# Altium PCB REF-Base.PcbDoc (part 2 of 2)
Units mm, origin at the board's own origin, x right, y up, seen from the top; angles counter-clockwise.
Board outline 48.01 x 58 mm, 4 copper layers (Top1, VCC, GND, Bottom2), stack 1.833 mm thick; 98 components, 129 nets, 444 pads, 192 vias.
Unrouted connection lines stored in the file: 57.
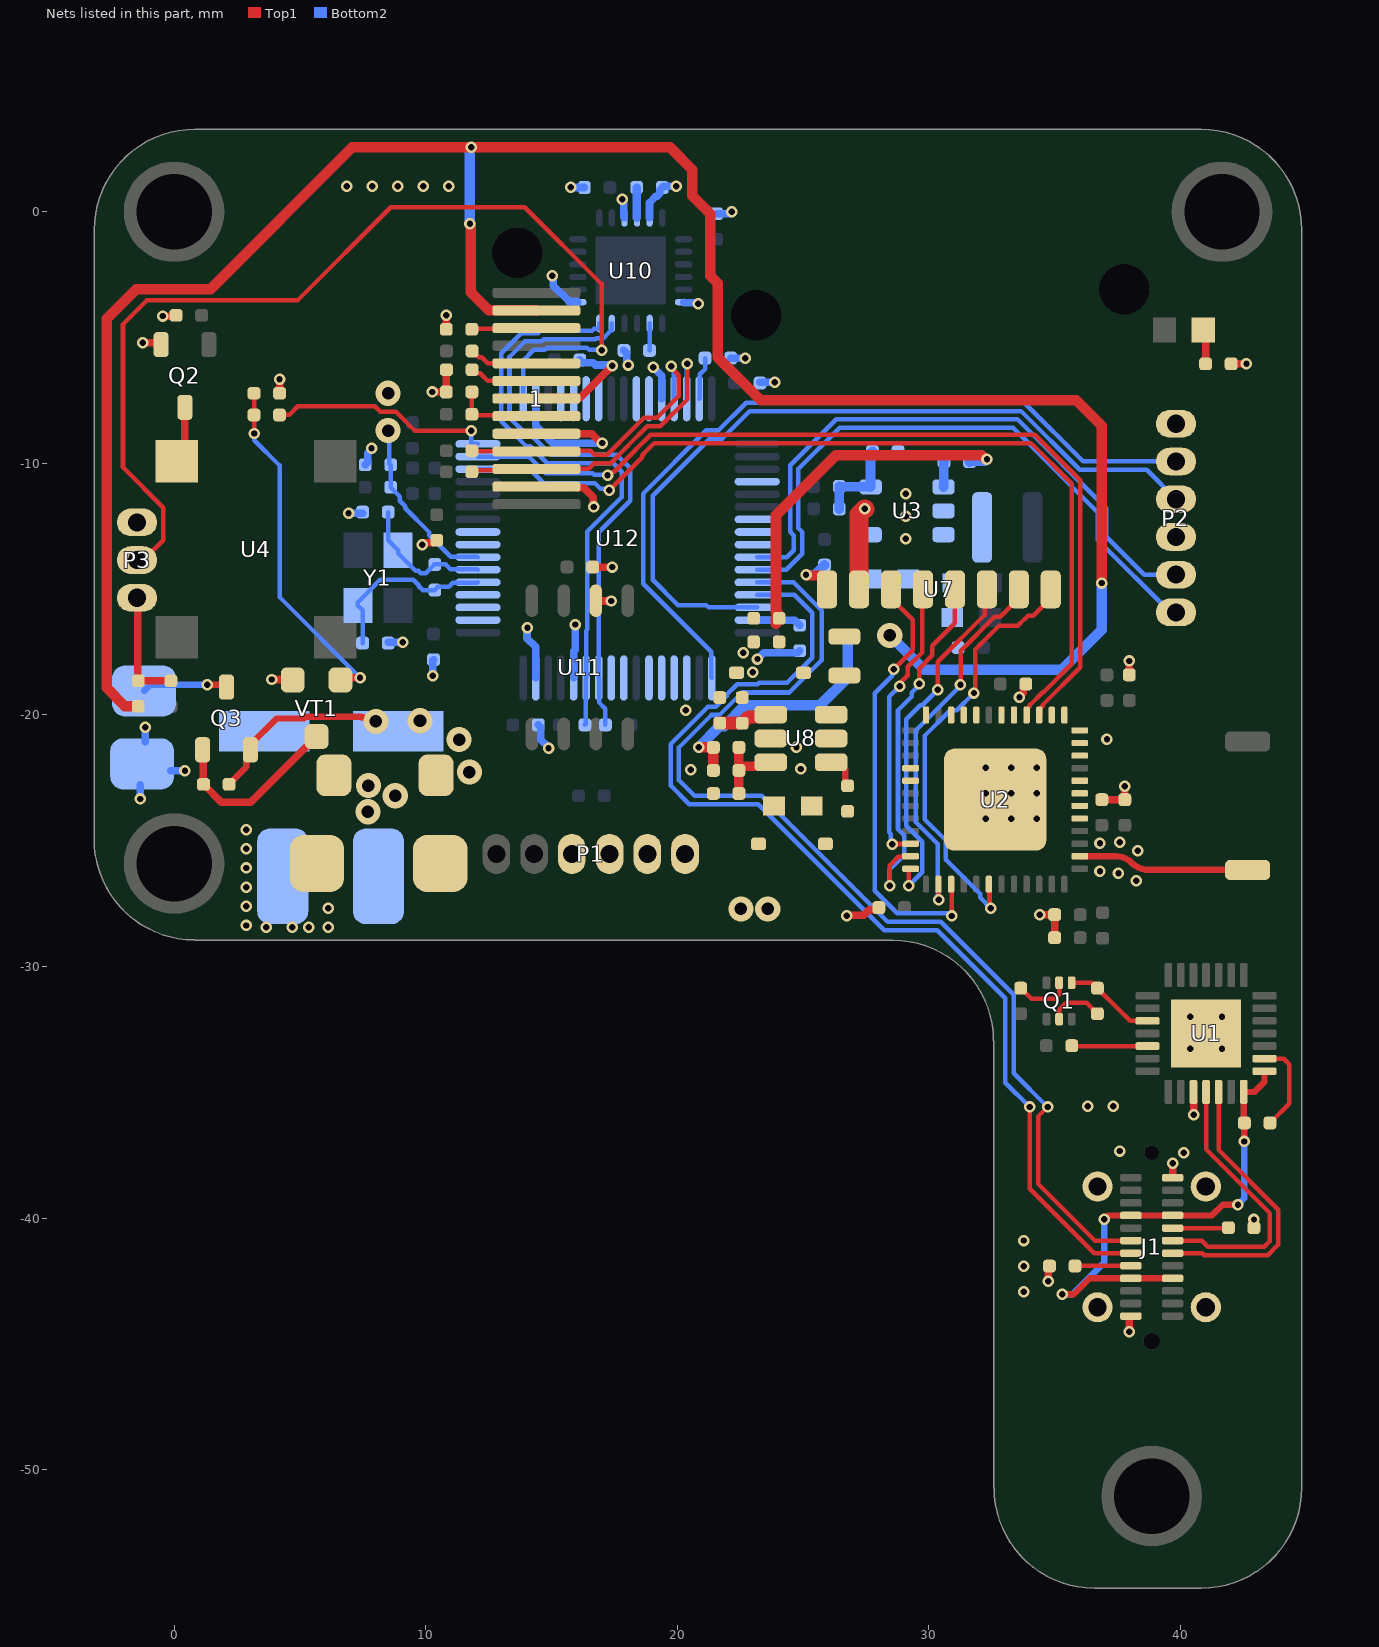
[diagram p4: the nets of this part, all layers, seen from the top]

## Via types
v1: diameter 0.457, hole 0.254, Top1 to Bottom2, tented both sides, 178 vias
v2: diameter 1, hole 0.5, Top1 to Bottom2, tented both sides, 12 vias
v3: diameter 0.457, hole 0.254, Top1 to Bottom2, 2 vias

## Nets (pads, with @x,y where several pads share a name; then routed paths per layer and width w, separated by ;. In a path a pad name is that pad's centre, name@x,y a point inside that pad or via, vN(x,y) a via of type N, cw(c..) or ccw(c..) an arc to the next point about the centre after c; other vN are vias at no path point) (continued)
GND: 1.7 1.9 1.12 C1.1 C2.1 C3.2 C4.1 C5.1 C6.2 C7.2 C9.2 C10.1 C14.1 C15.1 C16.1 C17.1 C18.1 C19.1 C20.2 C21.1 C22.1 C23.2 C24.1 C25.1 C26.1 C27.1 C28.1 C29.1 C30.1 C31.1 C34.1 C35.1 C36.1 C37.1 D3.1 D4.1 J1.A1 J1.B1 J1.S1 J1.S2 J1.S3 J1.S4 P1.3 P1.4 P2.1 P2.4 P3.3 pad.@4.318,-26.416 pad.@-1.27,-21.946 Q2.2 R8.2 R9.2 R10.1 R14.1 R15.2 R18.1 R22.2 R26.2 R35.1 U1.3 U1.29 U2.49 U3.2 U7.2 U8.2 U10.1 U10.9 U10.11 U10.18 U11.2 U12.18 U12.28 U12.60 U12.63 VT1.2 | length 51.8
  Top1 w0.3: v1(-1.245,-5.207) Q2.2@-0.686,-5.207 ; v1(-0.457,-4.144) R10.1@0.102,-4.144 ; v1(3.886,-18.593) VT1.2@4.445,-18.593 ; R15.2@4.191,-7.214 v1(4.191,-6.655) v1@4.242,-6.604 ; v1(9.859,-13.242) 9.901,-13.242 9.984,-13.16 10.335,-13.16 R26.2@10.439,-13.056 ; v1@10.236,-7.137 v1(10.262,-7.163) C26.1@10.82,-7.163 10.824,-7.159 10.824,-6.283 R22.2@10.827,-6.279 ; C27.1@10.82,-4.674 v1(10.82,-4.115) ; 1.9@14.402,-8.825 16.608,-8.825 16.976,-9.193 v1(17.018,-9.193) ; 1.7@14.402,-7.425 14.452,-7.375 16.171,-7.375 v1(17.424,-6.121) ; 1.12@15.949,-10.922 16,-10.973 16.282,-10.973 16.658,-11.349 16.658,-11.705 v1(16.688,-11.735) ; C18.1@16.711,-14.126 16.715,-14.122 v1(17.424,-14.122) ; U11.2@16.787,-15.472 v1(17.371,-15.472) ; v1(26.746,-27.991) 26.776,-27.961 27.419,-27.961 27.633,-27.747 27.93,-27.747 C37.1@28.016,-27.661 ; v1(33.604,-19.304) 33.604,-19.262 33.754,-19.112 33.754,-18.875 C22.1@33.884,-18.745 ; v1(34.417,-27.94) C2.1@35.001,-27.94 C1.1@35.001,-28.854 ; v1(34.747,-42.52) R9.2@34.747,-41.961 ; C19.1@36.881,-23.368 C21.1@37.795,-23.368 v1(37.795,-22.835) ; v1(37.973,-44.526) J1.A1@37.973,-43.967 ; C3.2@37.973,-18.415 v1(37.973,-17.856) ; J1.B1@39.7,-38.379 v1(39.7,-37.821) ; v1(40.538,-35.89) U1.3@40.538,-35.331 ; R18.1@42.069,-6.045 v1(42.628,-6.045)
  Top1 w0.762: U7.2@27.229,-15.011 27.229,-12.04 v1(27.457,-11.811)
  Bottom2 w0.3: v1(-1.346,-23.343) pad.@-1.346,-22.784 ; pad.@-1.151,-21.057 v1(-1.151,-20.498) ; pad.@-0.127,-22.225 v1(0.432,-22.225) ; v1(6.934,-11.989) C9.2@7.493,-11.989 ; C36.1@7.595,-10.058 7.699,-9.954 7.699,-9.59 7.849,-9.44 v1(7.849,-9.398) ; C7.2@8.507,-17.116 v1(9.091,-17.116) ; v1(10.287,-18.44) 10.287,-17.831 C28.1@10.312,-17.805 ; v1@14.028,-16.535 14.028,-16.949 14.378,-17.299 U12.63@14.378,-18.529 ; U12.18@14.378,-7.429 14.378,-8.51 15.06,-9.193 v1(17.018,-9.193) ; C29.1@14.478,-20.396 14.582,-20.5 14.582,-20.979 14.885,-21.282 v1(14.885,-21.324) ; v3(15.037,-2.54) 15.067,-2.57 15.067,-2.934 15.698,-3.566 16.028,-3.566 U10.1@16.053,-3.591 ; v1@15.748,0.991 15.773,0.965 C20.2@16.307,0.965 ; U12.60@15.878,-18.529 15.878,-17.48 15.951,-17.407 v1(15.951,-16.408) ; C31.1@16.129,-5.893 16.233,-5.997 16.657,-5.997 16.752,-6.091 17.394,-6.091 v1(17.424,-6.121) ; v1(17.821,0.492) 17.821,0.449 17.878,0.393 17.878,-0.216 U10.9@17.903,-0.241 ; C24.1@17.882,-5.512 17.986,-5.616 17.986,-5.921 v1@18.059,-5.994 ; U10.11@18.903,-0.241 18.898,-0.236 18.898,0.356 19.152,0.61 19.202,0.61 19.302,0.709 19.302,0.861 C23.2@19.406,0.965 19.456,1.016 v1(19.964,1.016) ; v1(19.053,-6.178) 19.053,-6.189 19.378,-6.514 U12.28@19.378,-7.429 ; U10.18@20.253,-3.591 20.278,-3.616 20.786,-3.616 v1(20.828,-3.658) ; C25.1@21.565,-0.076 22.098,-0.076 v1(22.174,0) ; C35.1@22.123,-5.817 v1(22.708,-5.817) ; v1(23.19,-17.78) 23.198,-17.78 23.444,-17.534 24.782,-17.534 C34.1@24.867,-17.45 ; C30.1@23.29,-6.778 v1(23.874,-6.778)
  other v1: 33.782,-42.926 33.782,-41.91 33.782,-40.894 42.926,-40.058 40.132,-37.412 37.592,-37.338 36.322,-35.56 37.338,-35.56 40.386,-33.274 41.656,-33.274 40.386,-32.004 41.656,-32.004 3.658,-28.448 4.699,-28.448 5.359,-28.448 6.121,-28.448 2.87,-28.372 6.121,-27.686 2.87,-27.61 2.87,-26.848 38.252,-26.594 37.541,-26.289 36.805,-26.213 2.87,-26.086 38.303,-25.4 2.87,-25.324 36.805,-25.095 37.592,-25.07 2.87,-24.562 32.258,-24.13 33.274,-24.13 34.29,-24.13 32.258,-23.114 33.274,-23.114 34.29,-23.114 20.539,-22.174 24.917,-22.149 32.258,-22.098 33.274,-22.098 34.29,-22.098 24.74,-21.285 37.084,-20.972 20.345,-19.812 22.997,-18.306 22.628,-17.534 14.046,-16.535 29.083,-12.995 29.083,-12.098 29.083,-11.201 18.059,-6.091 15.761,0.978 6.858,1.016 7.874,1.016 8.89,1.016 9.906,1.016 10.922,1.016
  other v2: 22.53,-27.711 23.597,-27.711 8.509,-7.213
GPIO2_1: U2.22
GPIO4_1: U2.24
GPIO5_1: U2.34 U7.4 | length 11.5
  Top1 w0.18: v1(28.549,-25.145) 28.563,-25.132 29.263,-25.132 U2.34@29.276,-25.118 ; v1(28.848,-18.854) 28.848,-18.746 29.166,-18.428 29.166,-18.091 29.74,-17.517 29.74,-15.04 U7.4@29.769,-15.011
  Bottom2 w0.18: v1(28.549,-25.145) 28.496,-25.092 28.496,-24.737 28.419,-24.661 28.419,-19.283 v1(28.848,-18.854)
GPIO9_1: U2.28
GPIO10_1: U2.29
GPIO12_1: U2.18
GPIO13_1: U2.20
GPIO14_1: U2.17
GPIO15_1: U2.21
GPIO18_1: U2.35 U7.5 | length 14.9
  Top1 w0.18: v1(28.448,-26.797) 28.448,-25.984 28.789,-25.643 29.251,-25.643 U2.35@29.276,-25.618 ; v1(29.616,-18.767) 29.616,-18.161 30.143,-17.634 30.143,-17.253 31.039,-16.358 U7.5@31.039,-15.011
  Bottom2 w0.18: v1(28.448,-26.797) 28.448,-26.137 29.02,-25.564 29.02,-24.791 28.776,-24.547 28.776,-19.814 29.315,-19.276 29.315,-19.122 29.616,-18.82 v1(29.616,-18.767)
GPIO19_1: U2.38 U7.7 | length 15.2
  Top1 w0.18: U2.38@30.389,-26.731 30.396,-26.738 30.396,-27.348 v1(30.404,-27.356) ; v1(31.259,-18.803) 31.267,-18.795 31.267,-17.45 32.614,-16.104 32.837,-16.104 33.579,-15.361 U7.7@33.579,-15.011
  Bottom2 w0.18: v1(30.404,-27.356) 30.351,-27.303 30.351,-25.131 29.489,-24.27 29.489,-20.61 31.259,-18.84 v1(31.259,-18.803)
GPIO21_1: U2.42 U7.8 | length 17.5
  Top1 w0.18: v1(31.796,-19.131) 31.838,-19.089 31.838,-17.413 32.791,-16.459 33.534,-16.459 33.807,-16.186 33.826,-16.186 33.96,-16.053 34.157,-16.053 34.849,-15.361 U7.8@34.849,-15.011 ; U2.42@32.389,-26.731 32.414,-26.756 32.414,-27.639 v1(32.461,-27.686)
  Bottom2 w0.18: v1(31.796,-19.131) 31.11,-19.817 30.85,-19.817 29.831,-20.836 29.831,-24.142 30.683,-24.994 30.683,-25.761 32.04,-27.118 32.04,-27.259 32.461,-27.68 v1(32.461,-27.686)
GPIO22_1: U2.39 U7.3 | length 17.7
  Top1 w0.18: U7.3@28.499,-15.011 28.499,-15.361 29.356,-16.218 29.356,-17.431 v1(28.6,-18.186) ; U2.39@30.889,-26.731 30.904,-26.745 30.904,-27.979 v1(30.918,-27.994)
  Bottom2 w0.18: v1(28.6,-18.186) 28.547,-18.239 28.547,-18.443 27.851,-19.139 27.851,-26.987 28.753,-27.889 30.739,-27.889 30.843,-27.994 v1(30.918,-27.994)
GPIO23_1: U2.36 U7.6 | length 14.5
  Top1 w0.18: v1(29.2,-26.797) 29.2,-26.143 29.225,-26.118 U2.36@29.276,-26.118 ; v1(30.353,-18.999) 30.353,-17.894 32.216,-16.031 32.216,-15.342 32.097,-15.223 U7.6@32.309,-15.011
  Bottom2 w0.18: v1(29.2,-26.797) 29.743,-26.254 29.743,-25.044 29.108,-24.409 29.108,-20.168 29.666,-19.61 29.742,-19.61 v1(30.353,-18.999)
GPIO25_1: U2.14
GPIO26_1: U2.15 U12.15 | length 35.7
  Top1 w0.18: v1(17.229,-10.467) 17.304,-10.467 17.443,-10.328 17.491,-10.328 18.357,-9.462 18.357,-9.449 18.944,-8.862 34.211,-8.862 36.017,-10.668 36.017,-18.109 34.522,-19.604 34.522,-19.66 34.424,-19.758 34.424,-19.97 U2.15@34.389,-20.005
  Bottom2 w0.18: U12.15@12.078,-9.729 14.102,-9.729 14.775,-10.403 16.641,-10.403 16.701,-10.463 17.225,-10.463 v1(17.229,-10.467)
GPIO27_1: U2.16 U12.14 | length 35.4
  Top1 w0.18: v1(17.302,-11.072) 18.611,-9.763 18.611,-9.678 18.689,-9.6 18.689,-9.586 19.082,-9.194 34.061,-9.194 35.685,-10.818 35.685,-17.971 34.562,-19.094 34.532,-19.094 34.022,-19.604 34.022,-19.66 33.924,-19.758 33.924,-19.97 U2.16@33.889,-20.005
  Bottom2 w0.18: U12.14@12.078,-10.229 14.132,-10.229 14.697,-10.795 16.73,-10.795 16.954,-11.019 17.249,-11.019 v1(17.302,-11.072)
GPIO32_1: U2.12
GPIO33_1: U2.13
GPIO34_1: U2.10
GPIO35_1: U2.11
GPIO37_1: U2.6
GPIO38_1: U2.7
I2C_SCL_1: U12.41
I2C_SDA_1: U12.40
IMU_SCL_1: R17.1 U10.23 U12.58 | length 23.6
  Bottom2 w0.18: R17.1@17.145,-20.396 17.145,-19.761 16.891,-19.507 16.891,-18.543 U12.58@16.878,-18.529 16.878,-12.739 18.126,-11.49 18.126,-10.201 17.594,-9.669 17.55,-9.669 17.545,-9.664 14.976,-9.664 14.161,-8.848 13.991,-8.848 13.333,-8.19 13.333,-5.77 13.948,-5.155 14.604,-5.155 14.695,-5.064 16.75,-5.064 16.78,-5.033 17.055,-5.033 17.27,-4.818 17.403,-4.685 U10.23@17.403,-4.441
IMU_SDA_1: R7.1 U10.24 U12.59 | length 23.5
  Bottom2 w0.18: R7.1@16.332,-20.396 16.355,-20.374 16.355,-18.552 U12.59@16.378,-18.529 16.378,-16.648 16.422,-16.603 16.422,-12.712 17.794,-11.34 17.794,-10.339 17.456,-10.001 17.413,-10.001 17.407,-9.996 14.838,-9.996 14.155,-9.313 13.986,-9.313 13.001,-8.327 13.001,-5.618 13.795,-4.823 14.466,-4.823 14.558,-4.732 16.612,-4.732 16.691,-4.653 16.87,-4.653 16.903,-4.62 U10.24@16.903,-4.441
Net1_3: 1.3 C27.2 | length 2.6
  Top1 w0.18: C27.2@11.836,-4.674 11.861,-4.649 14.377,-4.649 1.3@14.402,-4.625
Net1_5: 1.5 R23.1 | length 2.8
  Top1 w0.18: R23.1@11.843,-5.537 11.863,-5.537 12.113,-5.787 12.224,-5.787 12.462,-6.025 1.5@14.402,-6.025
Net1_6: 1.6 R22.1 | length 2.7
  Top1 w0.18: R22.1@11.843,-6.279 11.984,-6.421 12.169,-6.421 12.473,-6.725 1.6@14.402,-6.725
Net1_8: 1.8 C26.2 R21.1 | length 3.5
  Top1 w0.18: C26.2@11.836,-7.163 R21.1@11.836,-8.052 11.873,-8.088 14.365,-8.088 1.8@14.402,-8.125
NetA1_1: A1.1 U2.2 | length 6.8
  Top1 w0.254: U2.2@36.002,-25.618 37.436,-25.618 cw(c37.436,-26.521) 38.075,-25.883 ccw(c38.749,-25.208) 38.749,-26.162 A1.1@42.672,-26.162
NetC7_1: C7.1 R30.1 U12.5 Y1.3 | length 7.2
  Bottom2 w0.18: C7.1@7.493,-17.145 7.493,-15.845 Y1.3@7.303,-15.654 7.303,-15.529 8.201,-14.63 9.511,-14.63 9.731,-14.851 9.731,-14.888 9.881,-15.037 R30.1@10.363,-15.037 10.485,-14.915 10.917,-14.915 11.083,-14.749 12.058,-14.749 U12.5@12.078,-14.729
NetC8_1: C8.1 C12.1 D4.2 L1.1 U8.6
NetC8_2: C8.2 C12.2 U8.1 | length 2.2
  Top1 w0.52: C12.2@21.692,-20.328 C8.2@22.581,-20.328 22.831,-20.078 23.627,-20.078 U8.1@23.717,-19.988
NetC9_1: C9.1 R30.2 U12.6 Y1.1 | length 5.5
  Bottom2 w0.18: C9.1@8.509,-11.938 8.509,-13.061 Y1.1@8.903,-13.454 8.903,-13.579 9.601,-14.278 9.717,-14.278 9.803,-14.364 10.006,-14.364 10.349,-14.021 R30.2@10.363,-14.021 10.795,-14.021 10.984,-14.21 12.058,-14.21 U12.6@12.078,-14.229
NetC11_2: C11.2 R11.1 R14.2 U8.3 | length 3
  Top1 w0.381: R14.2@22.454,-23.122 C11.2@22.454,-21.293 ; R11.1@22.614,-22.047 23.558,-22.047 U8.3@23.717,-21.888
NetC13_1: C13.1 R33.1 R35.2 U3.5 | length 3.6
  Bottom2 w0.39: C13.1@26.441,-11.811 R33.1@26.441,-10.922 26.449,-10.93 27.68,-10.93 U3.5@27.687,-10.937 27.687,-9.6 R35.2@27.762,-9.525
NetC16_2: C16.2 D5.2 R16.1 U8.5
NetC23_1: C23.1 U10.10 | length 1.2
  Bottom2 w0.33: C23.1@18.39,0.965 18.396,0.959 18.396,-0.234 U10.10@18.403,-0.241
NetC24_2: C24.2 U10.20 | length 1.1
  Bottom2 w0.18: C24.2@18.898,-5.512 18.9,-5.509 18.9,-4.443 U10.20@18.903,-4.441
NetC34_2: C34.2 U12.47 | length 1.8
  Bottom2 w0.3: U12.47@23.178,-16.229 24.662,-16.229 C34.2@24.867,-16.434
NetC35_2: C35.2 U12.31 | length 1.7
  Bottom2 w0.18: U12.31@20.878,-7.429 20.901,-7.406 20.901,-6.463 21.115,-6.248 21.115,-5.825 C35.2@21.107,-5.817
NetJ1_A5: J1.A5 R9.1 | length 2.2
  Top1 w0.18: R9.1@35.826,-41.898 J1.A5@38.032,-41.898
NetJ1_B5: J1.B5 R8.1 | length 2.2
  Top1 w0.18: J1.B5@39.692,-40.398 41.898,-40.398 R8.1@41.91,-40.386
NetL2_1: L2.1 U3.3
NetLED1_C: LED1.C R18.2 | length 1.4
  Top1 w0.3: LED1.C@40.908,-4.699 41.002,-4.793 R18.2@41.002,-6.045
NetP3_1: P3.1 R27.1 R29.1 | length 4.6
  Top1 w0.3: P3.1@-1.473,-15.344 -1.448,-15.37 -1.448,-18.618 R29.1@-1.422,-18.644 R27.1@-0.127,-18.644
NetQ1_2: Q1.2 R4.2 | length 2.2
  Top1 w0.18: R4.2@33.655,-30.861 34.087,-31.293 35.001,-31.293 35.179,-31.115 Q1.2@35.179,-30.646
NetQ1_5: Q1.5 R6.2 | length 2.2
  Top1 w0.18: Q1.5@35.179,-32.092 35.179,-31.725 35.458,-31.445 36.271,-31.445 R6.2@36.703,-31.877
NetQ2_3: Q2.3 U4.2 | length 2.3
  Top1 w0.3: U4.2@0.101,-9.965 0.432,-9.634 Q2.3@0.432,-7.774
NetQ3_1: Q3.1 R12.1 VT1.3 | length 7.3
  Top1 w0.3: Q3.1@1.133,-21.388 1.151,-21.406 1.151,-22.741 R12.1@1.168,-22.758 1.88,-23.47 3.048,-23.47 5.657,-20.861 VT1.3@5.664,-20.861
NetR1_2: R1.2 U1.9 | length 3.7
  Top1 w0.18: U1.9@43.345,-33.664 44.104,-33.664 44.323,-33.884 44.323,-35.458 R1.2@43.561,-36.22
NetR3_2: R3.2 U1.26 | length 3
  Top1 w0.18: R3.2@35.704,-33.164 U1.26@38.697,-33.164
NetR13_2: R13.2 R15.1 VT1.1 | length 13.9
  Top1 w0.18: R15.1@3.175,-7.214 3.179,-7.218 3.179,-8.81 v1(3.183,-8.814)
  Top1 w0.3: VT1.1@6.614,-18.611 6.708,-18.517 v1(7.391,-18.517)
  Bottom2 w0.18: v1(3.183,-8.814) 3.183,-9.076 4.191,-10.084 4.191,-15.316 v1(7.391,-18.517)
NetR16_2: R16.2 U8.4 | length 1.4
  Top1 w0.254: U8.4@26.117,-21.888 26.391,-21.888 26.686,-22.182 26.686,-22.732 R16.2@26.772,-22.817
NetR34_1: R34.1 U3.1 | length 1
  Bottom2 w0.39: U3.1@30.583,-10.937 30.595,-10.925 30.595,-9.943 R34.1@30.607,-9.931
NRST_1: C36.2 R28.1 U12.7 | length 7.1
  Bottom2 w0.18: v2@8.509,-8.712 8.56,-8.763 8.56,-10.008 C36.2@8.611,-10.058 R28.1@8.611,-10.947 8.611,-10.962 8.968,-11.319 8.968,-11.486 9.19,-11.708 9.19,-11.786 10.135,-12.731 10.135,-12.852 10.992,-13.71 12.058,-13.71 U12.7@12.078,-13.729
  other v2: 8.509,-8.698
OLED_SCL_1: 1.10 R20.1 U12.29 | length 11.8
  Top1 w0.18: R20.1@11.836,-9.5 11.849,-9.512 14.389,-9.512 1.10@14.402,-9.525 14.419,-9.508 16.56,-9.508 16.716,-9.664 17.215,-9.664 17.692,-9.187 17.692,-9.173 18.669,-8.197 19.192,-8.197 20.064,-7.325 20.064,-6.492 v1@19.82,-6.248
  Bottom2 w0.18: v1(19.761,-6.147) 19.761,-6.222 19.855,-6.315 19.855,-7.406 U12.29@19.878,-7.429
OLED_SDA_1: 1.11 R19.1 U12.30 | length 12.6
  Top1 w0.18: R19.1@11.836,-10.338 11.893,-10.281 14.345,-10.281 14.413,-10.214 16.483,-10.214 16.701,-9.996 17.353,-9.996 18.025,-9.324 18.025,-9.311 18.806,-8.529 19.329,-8.529 20.396,-7.462 v1(20.396,-6.045)
  Bottom2 w0.18: U12.30@20.378,-7.429 20.387,-7.42 20.387,-6.054 v1(20.396,-6.045)
PA4_1: U12.20
PA6_1: U12.22
PB0_1: U12.26
PB1_1: U12.27
PC0_1: U12.8
PC1_1: U12.9
PC8_1: U12.39
PC13_1: U12.2
PC14_1: U12.3
PC15_1: U12.4
PWM_A1_1: R13.1 U12.16 | length 8.9
  Top1 w0.18: R13.1@4.191,-8.077 4.572,-8.077 4.913,-7.736 7.981,-7.736 8.201,-7.956 8.819,-7.956 9.576,-8.712 v1(11.811,-8.712)
  Bottom2 w0.18: v1(11.811,-8.712) 11.811,-9.174 11.866,-9.229 U12.16@12.078,-9.229
PWM_A2_1: P3.2 U12.17 | length 40.7
  Top1 w0.18: P3.2@-1.827,-13.845 P3.2@-1.473,-13.845 -1.223,-13.845 -0.431,-13.052 -0.431,-11.761 -2.032,-10.16 -2.032,-4.47 -1.087,-3.526 4.907,-3.526 8.611,0.178 13.945,0.178 16.993,-2.87 v1(16.993,-5.504)
  Bottom2 w0.18: U12.17@13.878,-7.429 13.878,-5.909 14.299,-5.488 14.742,-5.488 14.833,-5.396 16.409,-5.396 16.494,-5.481 16.97,-5.481 v1(16.993,-5.504)
PWM_B2_1: U12.36
RTS_1: Q1.1 R6.1 U1.24 | length 3.6
  Top1 w0.18: Q1.1@35.679,-30.646 36.488,-30.646 R6.1@36.703,-30.861 37.516,-31.674 38.006,-32.164 U1.24@38.697,-32.164
SENSOR_VN_1: U2.8
SENSOR_VP_1: U2.5
SPI1_MISO_1: U12.56
SPI1_MOSI_1: U12.23
SPI1_SCK_1: U12.21
SPI3_MISO_1: U12.52
SPI3_MOSI_1: U12.57
SPI3_SCK_1: U12.51
SWCLK_1: P2.2 U12.49 | length 32.1
  Bottom2 w0.18: U12.49@21.378,-18.529 21.355,-18.506 21.355,-17.494 18.644,-14.783 18.644,-11.201 21.16,-8.685 21.643,-8.685 22.74,-7.588 33.801,-7.588 36.139,-9.926 P2.2@39.827,-9.926
SWDIO_1: P2.3 U12.46 | length 31.6
  Bottom2 w0.18: U12.46@23.178,-15.729 21.248,-15.729 21.151,-15.633 20.027,-15.633 19.025,-14.63 19.025,-11.29 21.298,-9.017 21.781,-9.017 22.877,-7.92 33.663,-7.92 36.004,-10.262 38.663,-10.262 P2.3@39.827,-11.426
SWITCH_LED+_1: pad.@-1.194,-19.05 Q3.3 | length 3.4
  Top1 w0.254: v1(1.321,-18.796) 1.983,-18.796 Q3.3@2.083,-18.896
  Bottom2 w0.254: pad.@-1.194,-19.05 -0.94,-18.796 v1(1.321,-18.796)
UART1_Rx_1: P2.6 U12.43 | length 24.9
  Bottom2 w0.18: U12.43@23.178,-14.229 24.328,-14.229 24.968,-13.589 24.968,-12.731 24.82,-12.583 24.82,-10.22 26.454,-8.585 33.35,-8.585 33.833,-9.068 36.726,-11.961 36.726,-13.053 39.599,-15.926 P2.6@39.827,-15.926
UART1_Tx_1: P2.5 U12.42 | length 24.3
  Bottom2 w0.18: U12.42@23.178,-13.729 24.358,-13.729 24.636,-13.451 24.636,-12.869 24.487,-12.72 24.487,-10.082 26.317,-8.253 33.525,-8.253 37.059,-11.786 37.059,-12.916 38.569,-14.426 P2.5@39.827,-14.426
UART5_Rx_1: U12.54
UART5_Tx_1: U12.53
USB_DM_1: J1.A7 U12.44 | length 43.1
  Top1 w0.18: v1(34.722,-35.585) 34.343,-35.964 34.343,-38.636 36.605,-40.898 J1.A7@38.032,-40.898
  Bottom2 w0.18: U12.44@23.178,-14.729 24.623,-14.729 25.745,-15.851 25.745,-17.818 24.454,-19.109 22.573,-19.109 21.678,-20.004 21.36,-20.004 20.068,-21.296 20.068,-22.599 20.691,-23.221 23.361,-23.221 28.361,-28.222 30.48,-28.222 33.378,-31.119 33.378,-34.241 v1(34.722,-35.585)
USB_DP_1: J1.A6 U12.45 | length 42.9
  Top1 w0.18: v1(34.011,-35.585) 34.011,-38.837 36.572,-41.398 J1.A6@38.032,-41.398
  Bottom2 w0.18: U12.45@23.178,-15.229 24.653,-15.229 25.363,-15.94 25.363,-17.73 24.378,-18.715 23.254,-18.715 23.192,-18.777 22.38,-18.777 21.96,-19.197 21.96,-19.252 21.54,-19.672 21.222,-19.672 19.736,-21.158 19.736,-22.809 20.48,-23.554 23.224,-23.554 28.224,-28.554 30.342,-28.554 33.045,-31.257 33.045,-34.62 v1(34.011,-35.585)
USB_ESP_DM_1: J1.B7 U1.5 | length 11.5
  Top1 w0.18: J1.B7@39.692,-41.398 40.877,-41.398 40.956,-41.476 43.47,-41.476 43.893,-41.053 43.893,-39.668 41.521,-37.295 U1.5@41.521,-34.989
USB_ESP_DP_1: J1.B6 U1.4 | length 11
  Top1 w0.18: J1.B6@39.692,-40.898 40.847,-40.898 41.093,-41.144 43.333,-41.144 43.561,-40.916 43.561,-39.805 41.021,-37.265 U1.4@41.021,-34.989
VCC: C6.1 D2.2 D3.2 D5.1 Q3.2 R12.2 | length 8
  Top1 w0.254: R12.2@2.184,-22.758 2.874,-22.069 2.874,-21.547 Q3.2@3.033,-21.388 3.033,-21.188 4.079,-20.142 5.152,-20.142 5.215,-20.079 7.423,-20.079 7.436,-20.091 7.518,-20.091 7.541,-20.114 7.879,-20.114 v2(8.022,-20.257) ; D2.2@10.008,-21.996 D2.2@10.414,-22.403
  other v2: 11.74,-22.274 11.328,-20.98 9.775,-20.231
VCC_3V3_RD: R31.2 U7.1 | length 2.5
  Top1 w0.39: v1(25.121,-14.427) 25.139,-14.427 25.171,-14.459 25.754,-14.459 25.959,-14.664 U7.1@25.959,-15.011 U7.1@25.959,-15.361
  Bottom2 w0.39: v1(25.121,-14.427) 25.476,-14.427 R31.2@25.857,-14.046 R31.2@25.848,-14.037
VCC_5V: 1.2 C11.1 C14.2 C15.2 C17.2 L1.2 R11.2 R29.2 R34.2 U3.4 | length 118.1
  Top1 w0.42: R29.2@-1.422,-19.66 -1.43,-19.652 -1.956,-19.652 -2.683,-18.925 -2.683,-4.257 -1.499,-3.073 1.448,-3.073 7.087,2.565 19.71,2.565 20.599,1.676 20.599,0.631 21.315,-0.084 21.315,-2.537 21.615,-2.838 21.615,-5.791 23.317,-7.493 35.865,-7.493 36.881,-8.509 v1(36.881,-14.757) ; v1(11.76,-0.483) 11.786,-0.508 11.786,-3.2 12.5,-3.915 14.392,-3.915 1.2@14.402,-3.925 ; v1(20.853,-21.285) 20.857,-21.289 21.434,-21.289 C11.1@21.438,-21.293 R11.2@21.438,-22.208 ; C14.2@23.927,-16.377 C14.2@23.927,-16.162 ; C14.2@24.01,-16.162 24.01,-15.982 23.927,-15.899 23.927,-12.065 26.31,-9.681 32.103,-9.681 32.264,-9.843 v1(32.313,-9.843)
  Bottom2 w0.42: v1(11.76,-0.483) 11.76,2.505 11.811,2.555 v1(11.811,2.565) ; v1(20.853,-21.285) 21.682,-20.457 21.865,-20.457 22.713,-19.609 25.679,-19.609 26.772,-18.517 26.772,-16.993 ; v2(28.448,-16.84) 29.82,-18.212 35.281,-18.212 36.881,-16.612 v1(36.881,-14.757) ; R34.2@31.623,-9.931 31.667,-9.887 32.22,-9.887 32.264,-9.843 v1(32.313,-9.843)
VCC_IN: D2.1 P1.1 P1.2 pad.@8.128,-26.416
  other v2: 7.701,-23.849 8.793,-23.214 7.722,-22.809
VDD_USB: J1.A4 J1.A9 J1.B4 J1.B9 R1.1 U1.7 U1.8 | length 20.1
  Top1 w0.254: v1(35.306,-43.028) 35.763,-43.028 36.393,-42.398 J1.A4@38.032,-42.398 J1.B9@39.692,-42.398 ; v1(36.982,-40.056) 37.14,-39.898 J1.A9@38.032,-39.898 J1.B4@39.692,-39.898 41.255,-39.898 41.681,-39.472 v1(42.291,-39.472) ; R1.1@42.521,-36.196 U1.7@42.521,-34.989 42.939,-34.989 43.345,-34.582 U1.8@43.345,-34.164 ; v1(42.545,-36.957) R1.1@42.545,-36.22
  Bottom2 w0.254: v1(35.306,-43.028) 35.712,-43.028 36.982,-41.758 v1(36.982,-40.056) ; v1(42.291,-39.472) 42.545,-39.218 v1(42.545,-36.957)
pads on no net: 1.1 1.13 A1. J1. J1.A2 J1.A3 J1.A8 J1.A10 J1.A11 J1.A12 J1.B2 J1.B3 J1.B8 J1.B10 J1.B11 J1.B12 U1.1 U1.2 U1.6 U1.10 U1.11 U1.12 U1.13 U1.14 U1.15 U1.16 U1.17 U1.18 U1.19 U1.20 U1.21 U1.22 U1.23 U1.27 U2.26 U2.44 U2.45 U2.47 U2.48 U4.3 U4.4 U10. U10.2 U10.3 U10.4 U10.5 U10.6 U10.7 U10.12 U10.14 U10.15 U10.16 U10.17 U10.19 U10.21 U10.22 U11.5 U11.8 Y1.2 Y1.4
copper on no net:
  other v3: 18.11,-2.261

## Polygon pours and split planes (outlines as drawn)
GND on Top1 "NONET_L01_P-001" (solid, pour order 23): 2.769,-24.257 6.375,-24.257 6.579,-24.46 6.579,-27.229 6.731,-27.381 14.884,-27.381 15.062,-27.203 15.062,-24.003 15.265,-23.8 17.653,-23.8 18.009,-24.155 18.009,-28.981 2.489,-28.981 2.489,-24.536 2.794,-24.232
GND on Top1 "GND_L01_P014" (solid, pour order 14): 23.425,-15.731 23.425,-18.51 23.292,-18.644 21.615,-18.644 21.387,-18.872 21.209,-18.872 20.955,-19.126 20.955,-22.458 21.136,-22.639 21.895,-22.639 22.111,-22.855 22.111,-23.372 22.208,-23.47 22.987,-23.47 23.216,-23.241 23.216,-22.809 23.566,-22.458 24.328,-22.458 24.638,-22.149 24.638,-21.658 24.417,-21.438 22.979,-21.438 22.835,-21.293 22.835,-20.752 23.089,-20.498 24.892,-20.498 25.197,-20.803 25.197,-22.53 24.968,-22.758 24.536,-22.758 24.486,-22.809 24.486,-24.181 24.308,-24.359 23.064,-24.359 22.429,-23.724 21.29,-23.724 20.091,-22.525 20.091,-17.424 21.785,-15.731 23.546,-15.731
VCC_5V on Top1 "VCC_5V_L01_P022" (solid, pour order 22): 23.622,-17.331 23.622,-15.878 23.825,-15.674 25.072,-15.674 25.654,-16.256 28.905,-16.256 29.007,-16.358 29.007,-17.221 28.778,-17.45 23.741,-17.45 23.622,-17.331 23.622,-15.807 23.698,-15.731
NetC16_2 on Top1 "NETC16_2_L01_P010" (solid, pour order 10): 24.605,-22.985 24.605,-26.56 24.74,-26.695 27.635,-26.695 28.067,-26.264 28.067,-20.676 27.889,-20.498 25.298,-20.498 25.222,-20.574 25.222,-21.285 25.349,-21.412 27.051,-21.412 27.267,-21.629 27.267,-24.32 27.102,-24.486 26.314,-24.486 26.06,-24.232 26.06,-22.86 25.984,-22.784 24.805,-22.784
VCC on Top1 "VCC_L01_P017" (solid, pour order 17): 9.487,-22.39 8.709,-21.612 7.363,-21.612 7.15,-21.399 7.15,-20.079 7.696,-19.533 11.1,-19.533 13.818,-22.25 19.482,-22.25 21.031,-23.8 22.34,-23.8 23.153,-24.613 23.622,-24.613 23.927,-24.917 23.927,-25.806 23.774,-25.959 21.819,-25.959 21.191,-25.331 21.191,-24.597 21.105,-24.511 19.583,-24.511 18.491,-23.419 12.391,-23.419 11.972,-23.838 11.972,-26.433 11.735,-26.67 9.677,-26.67 9.487,-26.479
NetC8_1 on Top1 "NETC8_1_L01_P012" (solid, pour order 12): 21.539,-19.699 22.82,-19.699 23.132,-19.388 24.849,-19.388 25.07,-19.609 25.07,-20.168 25.248,-20.345 27.788,-20.345 28.042,-20.091 28.042,-17.805 27.864,-17.628 24.181,-17.628 23.944,-17.865 23.944,-18.489 23.502,-18.931 21.557,-18.931 21.361,-19.126 21.361,-19.634 21.407,-19.679 21.539,-19.679
NetC16_2 on Top1 "NETC16_2_L01_P011" (solid, pour order 11): 27.364,-23.325 27.432,-23.393 27.432,-24.74 27.356,-24.816 26.197,-24.816 25.875,-24.494 25.875,-23.258 25.941,-23.325
VCC_IN on Top1 "VCC_IN_L01_P006" (solid, pour order 6): 7.061,-26.721 7.061,-24.206 6.782,-23.927 5.305,-23.927 5.131,-23.753 5.131,-21.946 5.309,-21.768 7.341,-21.768 7.722,-22.149 8.585,-22.149 9.246,-22.809 9.246,-26.365 9.017,-26.594 7.239,-26.594 7.036,-26.391
VCC_5V on Bottom2 "VCC_5V_L04_P018" (solid, pour order 18): 29.108,-17.221 29.108,-16.18 28.346,-15.418 28.346,-12.522 28.042,-12.217 26.873,-12.217 26.34,-12.751 26.34,-17.12 26.645,-17.424 28.905,-17.424 29.134,-17.196
3V3 on Bottom2 "3V3_L04_P021" (solid, pour order 21): 31.75,-17.323 31.75,-14.351 31.852,-14.249 32.987,-14.249 33.165,-14.072 33.165,-10.828 33.299,-10.693 34.9,-10.693 35.077,-10.871 35.077,-17.475 34.849,-17.704 31.947,-17.704 31.794,-17.551
NetL2_1 on Bottom2 "NETL2_1_L04_P020" (solid, pour order 20): 31.153,-12.446 31.471,-12.128 31.471,-11.024 31.674,-10.82 31.674,-10.795 32.842,-10.795 32.995,-10.947 32.995,-13.911 32.936,-13.97 31.674,-13.97 31.141,-13.437 30.074,-13.437 29.947,-13.31 29.947,-12.523 30.023,-12.446
GND on Bottom2 "GND_L04_P019" (solid, pour order 19): 31.572,-14.174 30.988,-13.589 29.855,-13.589 29.703,-13.437 29.703,-12.486 29.87,-12.319 31.064,-12.319 31.242,-12.141 31.242,-11.582 31.064,-11.405 29.947,-11.405 29.693,-11.151 29.693,-9.119 29.54,-8.966 28.397,-8.966 28.27,-9.093 28.27,-10.389 28.654,-10.773 28.654,-15.218 29.616,-16.18 29.616,-17.45 29.921,-17.755 31.267,-17.755 31.572,-17.45
VCC_IN on Bottom2 "VCC_IN_L04_P015" (solid, pour order 15): 7.036,-27.051 7.036,-28.575 7.112,-28.651 21.488,-28.651 21.59,-28.55 21.59,-24.359 21.336,-24.105 18.44,-24.105 18.212,-24.333 18.212,-26.314 18.009,-26.518 8.611,-26.518 8.077,-27.051
GND on Bottom2 "GND_L04_P009" (solid, pour order 9): 4.928,-21.742 5.131,-21.539 6.248,-21.539 6.502,-21.285 6.502,-19.812 6.325,-19.634 2.533,-19.634 2.413,-19.914 2.413,-24.562 4.724,-24.562 4.928,-24.359
VCC on Bottom2 "VCC_L04_P008" (solid, pour order 8): 9.474,-22.454 8.636,-21.615 7.366,-21.615 7.036,-21.285 7.036,-20.193 7.264,-19.964 11.1,-19.964 12.116,-20.98 12.116,-23.08 11.828,-23.368 9.654,-23.368 9.474,-23.188
VCC_IN on Bottom2 "VCC_IN_L04_P004" (solid, pour order 4): 7.061,-27.076 7.061,-24.003 7.036,-23.978 5.283,-23.978 5.131,-23.825 5.131,-21.946 5.309,-21.768 7.341,-21.768 7.722,-22.149 8.611,-22.149 9.195,-22.733 9.195,-27.254 7.239,-27.254 7.036,-27.051
GND on Bottom2 "GND_L04_P002" (solid, pour order 2): 2.616,-24.308 6.502,-24.308 6.655,-24.46 6.655,-28.651 6.579,-28.727 2.139,-28.727 2.083,-28.671 2.083,-27.407 2.413,-27.076 2.413,-24.511
GND on GND (split plane): 166 vertices, not listed, extent -2.669,-54.21 44.319,2.772
3V3 on VCC (split plane): 164 vertices, not listed, extent -2.669,-54.21 44.319,2.772

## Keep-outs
Keep-Out Layer:
  lines w0.254: -3.18,-24.948 ccw(c0.82,-24.948) 0.82,-28.948 ; -3.172,-24.948 -3.172,-16.506 -3.172,-0.719 cw(c0.828,-0.719) 0.828,3.281 40.828,3.281 cw(c40.828,-0.719) 44.828,-0.719 44.828,-50.719 cw(c40.828,-50.719) 40.828,-54.719 36.594,-54.719 cw(c36.594,-50.719) 32.594,-50.719 ; 0.82,-28.956 28.571,-28.956 ; 28.571,-28.961 cw(c28.571,-32.961) 32.571,-32.961 ; 32.576,-50.737 32.576,-32.961

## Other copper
Top1:
  pour cut-out: 36.474,6.045 36.474,-6.833 24.384,-6.833 24.384,6.045
  pour cut-out: 46.228,-18.288 46.228,-29.21 38.608,-29.21 38.608,-18.288
  text "L1" at 41.372,-48.29 h1
Bottom2:
  pour cut-out: 36.474,5.944 36.474,-6.934 24.384,-6.934 24.384,5.944
  pour cut-out: 46.228,-18.288 46.228,-29.21 38.608,-29.21 38.608,-18.288
  text "L4" at 41.372,-48.29 h1
VCC (plane layer: these items are gaps in the copper):
  rectangle: 15.265,-24.079 17.145,-21.082
  rectangle: 2.083,-29.235 21.031,-23.8
  text "L2" at 41.372,-48.29 h1
GND (plane layer: these items are gaps in the copper):
  rectangle: 18.034,-27.254 21.751,-23.978
  rectangle: 14.732,-28.905 21.819,-26.772
  rectangle: 2.083,-29.235 15.138,-23.851
  text "L3" at 41.372,-48.29 h1

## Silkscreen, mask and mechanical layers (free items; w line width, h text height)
Top Overlay:
  text "Designed by            MUZI XIAOWEN" at 2.1,-0.99 h2
  text "V1.01" at 33.706,-48.565 h1.52
Bottom Overlay:
  lines w0.254: -3.054,-6 12,-6 12,3.288 ; 29.656,3.316 29.656,-6 44.735,-6
  text "+" at 16.229,-28.047 h3.81
Top Solder:
  rectangle: 24.282,-6.883 36.373,6.121
  rectangle: 38.608,-29.21 46.228,-18.288
Bottom Solder:
  rectangle: 24.282,-6.883 36.373,6.121
  rectangle: 38.608,-29.21 46.228,-18.288
Mechanical 1:
  lines w0.254: -3.18,-24.948 ccw(c0.82,-24.948) 0.82,-28.948 ; -3.172,-24.948 -3.172,-16.506 -3.172,-0.719 cw(c0.828,-0.719) 0.828,3.281 40.828,3.281 cw(c40.828,-0.719) 44.828,-0.719 44.828,-50.719 cw(c40.828,-50.719) 40.828,-54.719 36.594,-54.719 cw(c36.594,-50.719) 32.594,-50.719 ; 0.82,-28.956 28.571,-28.956 ; 28.571,-28.961 cw(c28.571,-32.961) 32.571,-32.961 ; 32.576,-50.737 32.576,-32.961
